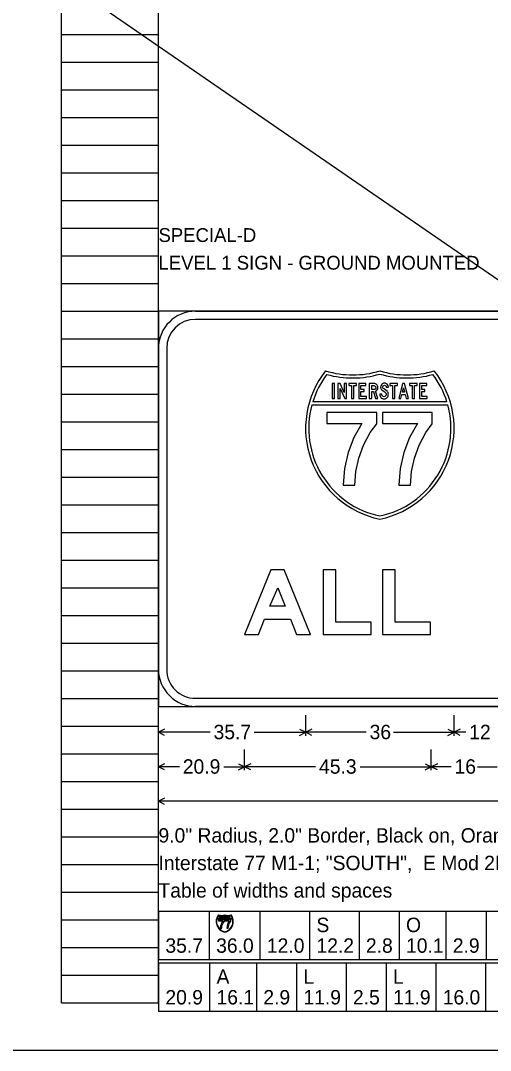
# Model space of a CAD drawing. Extents: x 1820207 to 1820557, y 740216 to 740315.
# Drawn here: x 1820490.8 to 1820495.55, y 740293.6 to 740304.02 of the extents above; entities that cross this region are included whole.
import ezdxf

# ---------------------------------------------------------------- set-up
doc = ezdxf.new("R2010")
doc.units = 0
for name, color, linetype in [('SC_Scratch1', 7, 'Continuous'), ('SC_Scratch2', 7, 'Continuous'), ('SC_Scratch3', 7, 'Continuous'), ('SC_Shading1', 7, 'Continuous'), ('SH_Text', 7, 'Continuous')]:
    doc.layers.add(name, color=color, linetype=linetype)

msp = doc.modelspace()

# ---------------------------------------------------------------- linework, layer by layer
at = {"layer": 'SC_Scratch1'}
for p, q in [((1820491.211, 740294.081), (1820491.211, 740314.241)), ((1820492.191, 740294.081), (1820492.191, 740314.241)), ((1820491.211, 740303.881), (1820492.191, 740303.881)), ((1820491.211, 740303.601), (1820492.191, 740303.601)), ((1820491.211, 740303.321), (1820492.191, 740303.321)), ((1820491.211, 740303.041), (1820492.191, 740303.041)), ((1820491.211, 740302.761), (1820492.191, 740302.761)), ((1820491.211, 740302.481), (1820492.191, 740302.481)), ((1820491.211, 740302.201), (1820492.191, 740302.201)), ((1820491.211, 740301.921), (1820492.191, 740301.921)), ((1820491.211, 740301.641), (1820492.191, 740301.641)), ((1820491.211, 740301.361), (1820492.191, 740301.361)), ((1820491.211, 740301.081), (1820492.191, 740301.081)), ((1820491.211, 740300.801), (1820492.191, 740300.801)), ((1820491.211, 740300.521), (1820492.191, 740300.521)), ((1820491.211, 740300.241), (1820492.191, 740300.241)), ((1820491.211, 740299.961), (1820492.191, 740299.961)), ((1820491.211, 740299.681), (1820492.191, 740299.681)), ((1820491.211, 740299.401), (1820492.191, 740299.401)), ((1820491.211, 740299.121), (1820492.191, 740299.121)), ((1820491.211, 740298.841), (1820492.191, 740298.841)), ((1820491.211, 740298.561), (1820492.191, 740298.561)), ((1820491.211, 740298.281), (1820492.191, 740298.281)), ((1820491.211, 740298.001), (1820492.191, 740298.001)), ((1820491.211, 740297.721), (1820492.191, 740297.721)), ((1820491.211, 740297.441), (1820492.191, 740297.441)), ((1820491.211, 740297.161), (1820492.191, 740297.161)), ((1820491.211, 740296.881), (1820492.191, 740296.881)), ((1820491.211, 740296.601), (1820492.191, 740296.601)), ((1820491.211, 740296.321), (1820492.191, 740296.321)), ((1820491.211, 740296.041), (1820492.191, 740296.041)), ((1820491.211, 740295.761), (1820492.191, 740295.761)), ((1820491.211, 740295.481), (1820492.191, 740295.481)), ((1820491.211, 740295.201), (1820492.191, 740295.201)), ((1820491.211, 740294.921), (1820492.191, 740294.921)), ((1820491.211, 740294.641), (1820492.191, 740294.641)), ((1820491.211, 740294.361), (1820492.191, 740294.361)), ((1820491.211, 740294.081), (1820492.191, 740294.081))]:
    msp.add_line(p, q, dxfattribs=at)
at = {"layer": 'SC_Scratch2'}
msp.add_lwpolyline([(1820476.451, 740314.601), (1820506.951, 740314.601), (1820506.951, 740293.601), (1820476.451, 740293.601)], close=True, dxfattribs=at)
at = {"layer": 'SC_Scratch3'}
for p, q in [((1820495.107, 740300.165), (1820493.751, 740300.165)), ((1820493.742, 740300.133), (1820495.116, 740300.133)), ((1820492.191, 740296.088), (1820492.191, 740297.046)), ((1820492.191, 740296.785), (1820492.191, 740296.994)), ((1820493.679, 740296.785), (1820493.679, 740296.994)), ((1820495.179, 740296.785), (1820495.179, 740296.994)), ((1820492.253, 740296.851), (1820492.191, 740296.82)), ((1820492.713, 740296.82), (1820492.191, 740296.82)), ((1820492.253, 740296.789), (1820492.191, 740296.82)), ((1820493.157, 740296.82), (1820493.679, 740296.82)), ((1820493.616, 740296.851), (1820493.679, 740296.82)), ((1820493.616, 740296.789), (1820493.679, 740296.82)), ((1820493.741, 740296.851), (1820493.679, 740296.82)), ((1820494.29, 740296.82), (1820493.679, 740296.82)), ((1820493.741, 740296.789), (1820493.679, 740296.82)), ((1820494.568, 740296.82), (1820495.179, 740296.82)), ((1820495.116, 740296.851), (1820495.179, 740296.82)), ((1820495.116, 740296.789), (1820495.179, 740296.82)), ((1820495.241, 740296.851), (1820495.179, 740296.82)), ((1820495.298, 740296.82), (1820495.179, 740296.82)), ((1820495.241, 740296.789), (1820495.179, 740296.82)), ((1820492.191, 740296.436), (1820492.191, 740296.645)), ((1820493.061, 740296.436), (1820493.061, 740296.645)), ((1820494.948, 740296.436), (1820494.948, 740296.645)), ((1820492.253, 740296.502), (1820492.191, 740296.471)), ((1820492.402, 740296.471), (1820492.191, 740296.471)), ((1820492.253, 740296.44), (1820492.191, 740296.471)), ((1820492.85, 740296.471), (1820493.061, 740296.471)), ((1820492.999, 740296.502), (1820493.061, 740296.471)), ((1820492.999, 740296.44), (1820493.061, 740296.471)), ((1820493.123, 740296.502), (1820493.061, 740296.471)), ((1820493.779, 740296.471), (1820493.061, 740296.471)), ((1820493.123, 740296.44), (1820493.061, 740296.471)), ((1820494.23, 740296.471), (1820494.948, 740296.471)), ((1820494.885, 740296.502), (1820494.948, 740296.471)), ((1820494.885, 740296.44), (1820494.948, 740296.471)), ((1820495.01, 740296.502), (1820494.948, 740296.471)), ((1820495.148, 740296.471), (1820494.948, 740296.471)), ((1820495.01, 740296.44), (1820494.948, 740296.471)), ((1820495.414, 740296.471), (1820495.614, 740296.471)), ((1820492.253, 740296.154), (1820492.191, 740296.123)), ((1820495.754, 740296.123), (1820492.191, 740296.123)), ((1820492.253, 740296.091), (1820492.191, 740296.123)), ((1820492.191, 740295.007), (1820492.191, 740294.519)), ((1820498.003, 740295.007), (1820492.191, 740295.007)), ((1820492.704, 740295.007), (1820492.704, 740294.519)), ((1820493.217, 740295.007), (1820493.217, 740294.519)), ((1820493.718, 740295.007), (1820493.718, 740294.519)), ((1820494.218, 740295.007), (1820494.218, 740294.519)), ((1820494.623, 740295.007), (1820494.623, 740294.519)), ((1820495.096, 740295.007), (1820495.096, 740294.519)), ((1820495.502, 740295.007), (1820495.502, 740294.519)), ((1820492.781, 740294.932), (1820492.941, 740294.932)), ((1820492.94, 740294.936), (1820492.782, 740294.936)), ((1820498.003, 740294.519), (1820492.191, 740294.519)), ((1820492.191, 740294.484), (1820492.191, 740293.996)), ((1820500.097, 740294.484), (1820492.191, 740294.484)), ((1820492.708, 740294.484), (1820492.708, 740293.996)), ((1820493.181, 740294.484), (1820493.181, 740293.996)), ((1820493.586, 740294.484), (1820493.586, 740293.996)), ((1820494.088, 740294.484), (1820494.088, 740293.996)), ((1820494.493, 740294.484), (1820494.493, 740293.996)), ((1820494.994, 740294.484), (1820494.994, 740293.996)), ((1820495.495, 740294.484), (1820495.495, 740293.996)), ((1820500.097, 740293.996), (1820492.191, 740293.996))]:
    msp.add_line(p, q, dxfattribs=at)
for points in [[(1820492.191, 740297.081), (1820499.691, 740297.081), (1820499.691, 740301.081), (1820492.191, 740301.081), (1820492.191, 740297.081), (1820492.191, 740297.081), (1820492.191, 740297.081)], [(1820492.566, 740301.081), (1820499.316, 740301.081)], [(1820499.316, 740300.998), (1820492.566, 740300.998)], [(1820492.191, 740297.456), (1820492.191, 740300.706)], [(1820492.274, 740300.706), (1820492.274, 740297.456)], [(1820492.274, 740300.706), (1820492.274, 740300.706), (1820492.274, 740300.706)], [(1820493.742, 740300.133), (1820493.742, 740300.133), (1820493.742, 740300.133)], [(1820492.566, 740297.165), (1820499.316, 740297.165)], [(1820492.566, 740297.165), (1820492.566, 740297.165), (1820492.566, 740297.165)], [(1820499.316, 740297.081), (1820492.566, 740297.081)]]:
    msp.add_lwpolyline(points, dxfattribs=at)
for points in [[(1820493.948, 740300.196), (1820493.97, 740300.196), (1820493.97, 740300.349), (1820493.948, 740300.349)], [(1820494.005, 740300.196), (1820494.026, 740300.196), (1820494.026, 740300.299), (1820494.074, 740300.196), (1820494.091, 740300.196), (1820494.091, 740300.349), (1820494.068, 740300.349), (1820494.068, 740300.258), (1820494.026, 740300.349), (1820494.005, 740300.349)], [(1820494.142, 740300.196), (1820494.164, 740300.196), (1820494.164, 740300.33), (1820494.193, 740300.33), (1820494.193, 740300.349), (1820494.114, 740300.349), (1820494.114, 740300.33), (1820494.142, 740300.33)], [(1820494.294, 740300.217), (1820494.238, 740300.217), (1820494.238, 740300.268), (1820494.27, 740300.268), (1820494.27, 740300.289), (1820494.238, 740300.289), (1820494.238, 740300.328), (1820494.288, 740300.328), (1820494.288, 740300.349), (1820494.215, 740300.349), (1820494.215, 740300.196), (1820494.294, 740300.196)], [(1820494.322, 740300.196), (1820494.346, 740300.196), (1820494.346, 740300.269), (1820494.366, 740300.269), (1820494.386, 740300.196), (1820494.408, 740300.196), (1820494.386, 740300.271), (1820494.396, 740300.277), (1820494.403, 740300.285), (1820494.407, 740300.295), (1820494.408, 740300.306), (1820494.408, 740300.315), (1820494.406, 740300.324), (1820494.402, 740300.331), (1820494.398, 740300.337), (1820494.392, 740300.342), (1820494.385, 740300.346), (1820494.377, 740300.348), (1820494.368, 740300.349), (1820494.322, 740300.349)], [(1820494.346, 740300.289), (1820494.346, 740300.328), (1820494.368, 740300.328), (1820494.376, 740300.327), (1820494.382, 740300.323), (1820494.386, 740300.316), (1820494.388, 740300.308), (1820494.387, 740300.3), (1820494.383, 740300.294), (1820494.377, 740300.29), (1820494.369, 740300.289)], [(1820494.428, 740300.242), (1820494.428, 740300.24), (1820494.429, 740300.231), (1820494.431, 740300.222), (1820494.435, 740300.214), (1820494.44, 740300.207), (1820494.446, 740300.201), (1820494.454, 740300.196), (1820494.462, 740300.194), (1820494.471, 740300.193), (1820494.481, 740300.194), (1820494.489, 740300.196), (1820494.496, 740300.201), (1820494.503, 740300.207), (1820494.508, 740300.214), (1820494.512, 740300.222), (1820494.514, 740300.23), (1820494.515, 740300.24), (1820494.514, 740300.248), (1820494.511, 740300.257), (1820494.507, 740300.265), (1820494.501, 740300.272), (1820494.489, 740300.282), (1820494.471, 740300.295), (1820494.46, 740300.303), (1820494.457, 740300.308), (1820494.456, 740300.313), (1820494.458, 740300.32), (1820494.462, 740300.326), (1820494.468, 740300.33), (1820494.475, 740300.331), (1820494.482, 740300.33), (1820494.488, 740300.326), (1820494.491, 740300.321), (1820494.493, 740300.313), (1820494.515, 740300.313), (1820494.511, 740300.329), (1820494.503, 740300.341), (1820494.497, 740300.346), (1820494.49, 740300.349), (1820494.483, 740300.351), (1820494.474, 740300.352), (1820494.466, 740300.351), (1820494.459, 740300.349), (1820494.453, 740300.345), (1820494.447, 740300.34), (1820494.438, 740300.327), (1820494.435, 740300.312), (1820494.436, 740300.305), (1820494.438, 740300.298), (1820494.442, 740300.291), (1820494.447, 740300.285), (1820494.472, 740300.267), (1820494.481, 740300.26), (1820494.487, 740300.255), (1820494.492, 740300.247), (1820494.493, 740300.239), (1820494.492, 740300.23), (1820494.487, 740300.223), (1820494.48, 740300.217), (1820494.471, 740300.215), (1820494.462, 740300.217), (1820494.455, 740300.223), (1820494.45, 740300.232), (1820494.449, 740300.242)], [(1820494.558, 740300.196), (1820494.58, 740300.196), (1820494.58, 740300.33), (1820494.608, 740300.33), (1820494.608, 740300.349), (1820494.53, 740300.349), (1820494.53, 740300.33), (1820494.558, 740300.33)], [(1820494.619, 740300.196), (1820494.641, 740300.196), (1820494.651, 740300.238), (1820494.684, 740300.238), (1820494.695, 740300.196), (1820494.718, 740300.196), (1820494.679, 740300.349), (1820494.657, 740300.349)], [(1820494.657, 740300.26), (1820494.667, 740300.304), (1820494.679, 740300.26)], [(1820494.756, 740300.196), (1820494.778, 740300.196), (1820494.778, 740300.33), (1820494.807, 740300.33), (1820494.807, 740300.349), (1820494.728, 740300.349), (1820494.728, 740300.33), (1820494.756, 740300.33)], [(1820494.908, 740300.217), (1820494.852, 740300.217), (1820494.852, 740300.268), (1820494.884, 740300.268), (1820494.884, 740300.289), (1820494.852, 740300.289), (1820494.852, 740300.328), (1820494.902, 740300.328), (1820494.902, 740300.349), (1820494.83, 740300.349), (1820494.83, 740300.196), (1820494.908, 740300.196)], [(1820494.058, 740299.321), (1820494.177, 740299.321), (1820494.186, 740299.459), (1820494.215, 740299.594), (1820494.264, 740299.725), (1820494.332, 740299.853), (1820494.397, 740299.941), (1820494.397, 740300.056), (1820493.893, 740300.056), (1820493.893, 740299.946), (1820494.248, 740299.946), (1820494.166, 740299.802), (1820494.107, 740299.65), (1820494.071, 740299.489)], [(1820494.62, 740299.321), (1820494.739, 740299.321), (1820494.749, 740299.459), (1820494.778, 740299.594), (1820494.826, 740299.725), (1820494.894, 740299.853), (1820494.959, 740299.941), (1820494.959, 740300.056), (1820494.455, 740300.056), (1820494.455, 740299.946), (1820494.81, 740299.946), (1820494.728, 740299.802), (1820494.67, 740299.65), (1820494.633, 740299.489)], [(1820493.061, 740297.81), (1820493.201, 740297.81), (1820493.263, 740297.965), (1820493.524, 740297.965), (1820493.586, 740297.81), (1820493.727, 740297.81), (1820493.462, 740298.464), (1820493.326, 740298.464)], [(1820493.854, 740297.81), (1820494.342, 740297.81), (1820494.342, 740297.933), (1820493.983, 740297.933), (1820493.983, 740298.464), (1820493.854, 740298.464)], [(1820494.454, 740297.81), (1820494.942, 740297.81), (1820494.942, 740297.933), (1820494.583, 740297.933), (1820494.583, 740298.464), (1820494.454, 740298.464)], [(1820493.317, 740298.097), (1820493.397, 740298.282), (1820493.471, 740298.097)], [(1820492.805, 740294.94), (1820492.808, 740294.94), (1820492.808, 740294.957), (1820492.805, 740294.957)], [(1820492.812, 740294.94), (1820492.814, 740294.94), (1820492.814, 740294.952), (1820492.82, 740294.94), (1820492.822, 740294.94), (1820492.822, 740294.957), (1820492.819, 740294.957), (1820492.819, 740294.947), (1820492.814, 740294.957), (1820492.812, 740294.957)], [(1820492.828, 740294.94), (1820492.83, 740294.94), (1820492.83, 740294.955), (1820492.834, 740294.955), (1820492.834, 740294.957), (1820492.824, 740294.957), (1820492.824, 740294.955), (1820492.828, 740294.955)], [(1820492.845, 740294.942), (1820492.839, 740294.942), (1820492.839, 740294.948), (1820492.843, 740294.948), (1820492.843, 740294.95), (1820492.839, 740294.95), (1820492.839, 740294.955), (1820492.845, 740294.955), (1820492.845, 740294.957), (1820492.836, 740294.957), (1820492.836, 740294.94), (1820492.845, 740294.94)], [(1820492.849, 740294.94), (1820492.851, 740294.94), (1820492.851, 740294.948), (1820492.854, 740294.948), (1820492.856, 740294.94), (1820492.859, 740294.94), (1820492.856, 740294.948), (1820492.857, 740294.949), (1820492.858, 740294.95), (1820492.858, 740294.951), (1820492.859, 740294.952), (1820492.859, 740294.953), (1820492.858, 740294.954), (1820492.858, 740294.955), (1820492.857, 740294.956), (1820492.857, 740294.957), (1820492.856, 740294.957), (1820492.855, 740294.957), (1820492.854, 740294.957), (1820492.849, 740294.957)], [(1820492.851, 740294.95), (1820492.851, 740294.955), (1820492.854, 740294.955), (1820492.855, 740294.955), (1820492.856, 740294.954), (1820492.856, 740294.954), (1820492.856, 740294.953), (1820492.856, 740294.952), (1820492.856, 740294.951), (1820492.855, 740294.95), (1820492.854, 740294.95)], [(1820492.861, 740294.945), (1820492.861, 740294.945), (1820492.861, 740294.944), (1820492.861, 740294.943), (1820492.862, 740294.942), (1820492.862, 740294.941), (1820492.863, 740294.94), (1820492.864, 740294.94), (1820492.865, 740294.939), (1820492.866, 740294.939), (1820492.867, 740294.939), (1820492.868, 740294.94), (1820492.869, 740294.94), (1820492.87, 740294.941), (1820492.87, 740294.942), (1820492.871, 740294.943), (1820492.871, 740294.944), (1820492.871, 740294.945), (1820492.871, 740294.946), (1820492.871, 740294.947), (1820492.87, 740294.948), (1820492.869, 740294.948), (1820492.868, 740294.95), (1820492.866, 740294.951), (1820492.865, 740294.952), (1820492.864, 740294.953), (1820492.864, 740294.953), (1820492.864, 740294.954), (1820492.865, 740294.955), (1820492.866, 740294.955), (1820492.866, 740294.955), (1820492.867, 740294.955), (1820492.868, 740294.955), (1820492.868, 740294.954), (1820492.869, 740294.953), (1820492.871, 740294.953), (1820492.871, 740294.955), (1820492.87, 740294.956), (1820492.869, 740294.957), (1820492.868, 740294.957), (1820492.867, 740294.958), (1820492.866, 740294.958), (1820492.865, 740294.958), (1820492.865, 740294.957), (1820492.864, 740294.957), (1820492.863, 740294.956), (1820492.862, 740294.955), (1820492.862, 740294.953), (1820492.862, 740294.952), (1820492.862, 740294.951), (1820492.863, 740294.951), (1820492.863, 740294.95), (1820492.866, 740294.948), (1820492.867, 740294.947), (1820492.868, 740294.946), (1820492.868, 740294.946), (1820492.869, 740294.945), (1820492.868, 740294.944), (1820492.868, 740294.943), (1820492.867, 740294.942), (1820492.866, 740294.942), (1820492.865, 740294.942), (1820492.864, 740294.943), (1820492.864, 740294.944), (1820492.863, 740294.945)], [(1820492.876, 740294.94), (1820492.879, 740294.94), (1820492.879, 740294.955), (1820492.882, 740294.955), (1820492.882, 740294.957), (1820492.873, 740294.957), (1820492.873, 740294.955), (1820492.876, 740294.955)], [(1820492.883, 740294.94), (1820492.886, 740294.94), (1820492.887, 740294.944), (1820492.891, 740294.944), (1820492.892, 740294.94), (1820492.895, 740294.94), (1820492.89, 740294.957), (1820492.888, 740294.957)], [(1820492.888, 740294.947), (1820492.889, 740294.952), (1820492.89, 740294.947)], [(1820492.899, 740294.94), (1820492.902, 740294.94), (1820492.902, 740294.955), (1820492.905, 740294.955), (1820492.905, 740294.957), (1820492.896, 740294.957), (1820492.896, 740294.955), (1820492.899, 740294.955)], [(1820492.917, 740294.942), (1820492.91, 740294.942), (1820492.91, 740294.948), (1820492.914, 740294.948), (1820492.914, 740294.95), (1820492.91, 740294.95), (1820492.91, 740294.955), (1820492.916, 740294.955), (1820492.916, 740294.957), (1820492.908, 740294.957), (1820492.908, 740294.94), (1820492.917, 740294.94)], [(1820492.818, 740294.838), (1820492.832, 740294.838), (1820492.833, 740294.854), (1820492.836, 740294.87), (1820492.842, 740294.885), (1820492.85, 740294.9), (1820492.857, 740294.91), (1820492.857, 740294.923), (1820492.799, 740294.923), (1820492.799, 740294.911), (1820492.84, 740294.911), (1820492.83, 740294.894), (1820492.824, 740294.876), (1820492.819, 740294.857)], [(1820492.883, 740294.838), (1820492.897, 740294.838), (1820492.898, 740294.854), (1820492.902, 740294.87), (1820492.907, 740294.885), (1820492.915, 740294.9), (1820492.923, 740294.91), (1820492.923, 740294.923), (1820492.864, 740294.923), (1820492.864, 740294.911), (1820492.905, 740294.911), (1820492.896, 740294.894), (1820492.889, 740294.876), (1820492.885, 740294.857)]]:
    msp.add_lwpolyline(points, close=True, dxfattribs=at)
for centre, radius, start, end in [((1820492.566, 740300.706), 0.375, 90.0002, 179.9999), ((1820492.566, 740300.706), 0.292, 90.0002, 179.9998), ((1820494.616, 740299.896), 0.938, 141.669, 258.463), ((1820494.616, 740299.896), 0.938, 141.669, 258.463), ((1820494.155, 740301.374), 0.938, 253.009, 286.9911), ((1820494.155, 740301.374), 0.938, 253.009, 286.9911), ((1820494.241, 740299.896), 0.938, 281.5371, 38.3311), ((1820494.703, 740301.374), 0.938, 253.009, 286.9911), ((1820494.241, 740299.896), 0.938, 281.5371, 38.3311), ((1820494.703, 740301.374), 0.938, 253.009, 286.9911), ((1820494.616, 740299.896), 0.906, 142.9959, 162.7366), ((1820494.152, 740301.374), 0.969, 254.4391, 286.5746), ((1820494.705, 740301.374), 0.969, 253.4255, 285.561), ((1820494.241, 740299.896), 0.906, 17.2633, 37.0041), ((1820494.616, 740299.895), 0.906, 164.7534, 258.0705), ((1820494.241, 740299.895), 0.906, 281.9296, 15.2467), ((1820492.566, 740297.456), 0.375, 179.9998, 270.0001), ((1820492.566, 740297.456), 0.292, 179.9999, 270.0001), ((1820492.883, 740294.905), 0.109, 141.669, 258.463), ((1820492.883, 740294.905), 0.105, 142.9959, 162.7366), ((1820492.829, 740295.076), 0.109, 253.009, 286.9911), ((1820492.829, 740295.076), 0.113, 254.4391, 286.5746), ((1820492.839, 740294.905), 0.109, 281.5371, 38.3311), ((1820492.893, 740295.076), 0.109, 253.009, 286.9911), ((1820492.893, 740295.076), 0.113, 253.4255, 285.561), ((1820492.839, 740294.905), 0.105, 17.2633, 37.0041), ((1820492.883, 740294.905), 0.105, 164.7534, 258.0705), ((1820492.839, 740294.905), 0.105, 281.9296, 15.2467)]:
    msp.add_arc(centre, radius, start, end, dxfattribs=at)
at = {"layer": 'SC_Shading1'}
msp.add_lwpolyline([(1820476.451, 740314.601), (1820506.951, 740293.601)], dxfattribs=at)

# ---------------------------------------------------------------- texts
at = {"layer": 'SC_Scratch3'}
for s, height, p in [('35.7', 0.1458, (1820492.748, 740296.75)), ('36', 0.1458, (1820494.325, 740296.75)), ('12', 0.1458, (1820495.332, 740296.75)), ('20.9', 0.1458, (1820492.437, 740296.401)), ('45.3', 0.1458, (1820493.814, 740296.401)), ('16', 0.1458, (1820495.183, 740296.401)), ('9.0" Radius, 2.0" Border, Black on, Orange;', 0.14583, (1820492.191, 740295.704)), ('Interstate 77 M1-1; "SOUTH",  E Mod 2K; "ALL LANES",  E Mod 2K;', 0.14583, (1820492.191, 740295.425)), ('Table of widths and spaces', 0.14583, (1820492.191, 740295.147)), ('S', 0.146, (1820493.788, 740294.798)), ('O', 0.146, (1820494.693, 740294.798)), ('35.7', 0.1458, (1820492.261, 740294.589)), ('36.0', 0.1458, (1820492.774, 740294.589)), ('12.0', 0.1458, (1820493.287, 740294.589)), ('12.2', 0.1458, (1820493.788, 740294.589)), ('2.8', 0.1458, (1820494.288, 740294.589)), ('10.1', 0.1458, (1820494.693, 740294.589)), ('2.9', 0.1458, (1820495.166, 740294.589)), ('A', 0.146, (1820492.778, 740294.275)), ('L', 0.146, (1820493.656, 740294.275)), ('L', 0.146, (1820494.562, 740294.275)), ('20.9', 0.1458, (1820492.261, 740294.066)), ('16.1', 0.1458, (1820492.778, 740294.066)), ('2.9', 0.1458, (1820493.251, 740294.066)), ('11.9', 0.1458, (1820493.656, 740294.066)), ('2.5', 0.1458, (1820494.157, 740294.066)), ('11.9', 0.1458, (1820494.562, 740294.066)), ('16.0', 0.1458, (1820495.064, 740294.066))]:
    msp.add_text(s, height=height, dxfattribs=at).set_placement(p)
at = {"layer": 'SH_Text'}
for s, p in [('SPECIAL-D', (1820492.191, 740301.781)), ('LEVEL 1 SIGN - GROUND MOUNTED', (1820492.191, 740301.501))]:
    msp.add_text(s, height=0.14, dxfattribs=at).set_placement(p)

doc.saveas('drawing.dxf')
